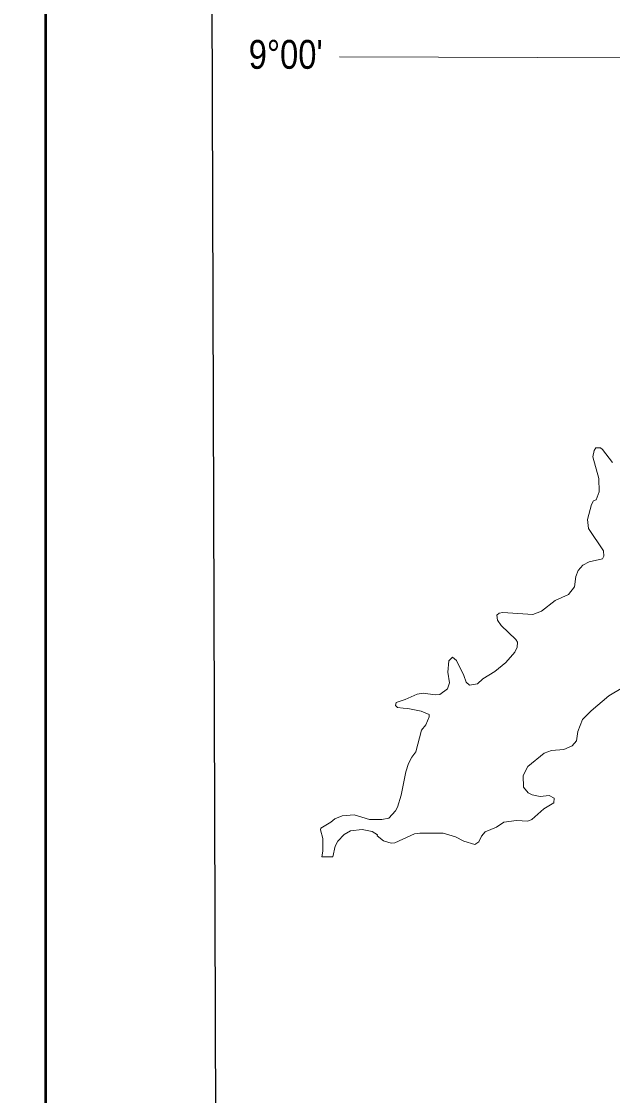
# Model space of a CAD drawing. Extents: x -1643653 to 4543381, y 1624270 to 13878484.
# Drawn here: x 559789 to 570038, y 8987135 to 9005760 of the extents above; entities that cross this region are included whole.
import ezdxf
from ezdxf.enums import TextEntityAlignment as Align

# ---------------------------------------------------------------- set-up
doc = ezdxf.new("R2010")
doc.units = 0
doc.header["$LTSCALE"] = 200
for name, color, linetype, lineweight in [('1', 7, 'Continuous', 13), ('25', 7, 'Continuous', 13), ('3', 7, 'Continuous', 13), ('60', 7, 'Continuous', 13)]:
    doc.layers.add(name, color=color, linetype=linetype, lineweight=lineweight)
doc.layers.add('46', color=7, linetype='Continuous')

msp = doc.modelspace()

# ---------------------------------------------------------------- linework, layer by layer
at = {"layer": '1'}
msp.add_lwpolyline([(565303.2, 9005146.6), (664889.8, 9004806.7), (719872.1, 9004543.9), (790635.8, 9004109)], dxfattribs=at)
at = {"layer": '25'}
for points in [[(570039.3, 8998110.8), (569862.2, 8998339.7), (569828.8, 8998363.9), (569747.5, 8998367.9), (569719.3, 8998318.1), (569695.6, 8998210), (569803.5, 8997832.4), (569805.7, 8997600.4), (569753.7, 8997466.5), (569708.6, 8997447), (569671.8, 8997384.4), (569607, 8997125.3), (569624.2, 8996969.4), (569883.5, 8996580.5), (569890, 8996489.7), (569862.1, 8996442.2), (569634.2, 8996387.6), (569524.8, 8996331.6), (569444.9, 8996241), (569401.6, 8996135.2), (569377.7, 8995955.6), (569276.2, 8995821.7), (569042.7, 8995719.9), (568806.8, 8995531.7), (568653.5, 8995475.6), (568134.7, 8995512.3), (568072.2, 8995501.6), (568030.8, 8995462.5), (568041.7, 8995378.5), (568108.6, 8995287.8), (568364, 8995043), (568387.6, 8994997.6), (568385.5, 8994911.7), (568342.3, 8994825.1), (568190.7, 8994643.1), (567996.1, 8994487.5), (567788.8, 8994357.9), (567698, 8994275.9), (567560, 8994252.1), (567499.2, 8994304.1), (567462.2, 8994418.7), (567330.6, 8994677.7), (567263.6, 8994734), (567200.7, 8994675.1), (567183.6, 8994478), (567209.4, 8994288.5), (567174.9, 8994185.2), (567041.5, 8994087.6), (566962.8, 8994081.3), (566755.8, 8994109.3), (566652.7, 8994094.4), (566443.9, 8994001.2), (566287.2, 8993950.5), (566277.5, 8993895.3), (566309.1, 8993863.6), (566406.3, 8993853.8)], [(570039.3, 8998110.8), (569862.2, 8998339.7), (569828.8, 8998363.9), (569747.5, 8998367.9), (569719.3, 8998318.1), (569695.6, 8998210), (569803.5, 8997832.4), (569805.7, 8997600.4), (569753.7, 8997466.5), (569708.6, 8997447), (569671.8, 8997384.4), (569607, 8997125.3), (569624.2, 8996969.4), (569883.5, 8996580.5), (569890, 8996489.7), (569862.1, 8996442.2), (569634.2, 8996387.6), (569524.8, 8996331.6), (569444.9, 8996241), (569401.6, 8996135.2), (569377.7, 8995955.6), (569276.2, 8995821.7), (569042.7, 8995719.9), (568806.8, 8995531.7), (568653.5, 8995475.6), (568134.7, 8995512.3), (568072.2, 8995501.6), (568030.8, 8995462.5), (568041.7, 8995378.5), (568108.6, 8995287.8), (568364, 8995043), (568387.6, 8994997.6), (568385.5, 8994911.7), (568342.3, 8994825.1), (568190.7, 8994643.1), (567996.1, 8994487.5), (567788.8, 8994357.9), (567698, 8994275.9), (567560, 8994252.1), (567499.2, 8994304.1), (567462.2, 8994418.7), (567330.6, 8994677.7), (567263.6, 8994734), (567200.7, 8994675.1), (567183.6, 8994478), (567209.4, 8994288.5), (567174.9, 8994185.2), (567041.5, 8994087.6), (566962.8, 8994081.3), (566755.8, 8994109.3), (566652.7, 8994094.4), (566443.9, 8994001.2), (566287.2, 8993950.5), (566277.5, 8993895.3), (566309.1, 8993863.6), (566406.3, 8993853.8)], [(568487.1, 8992684.5), (568569.1, 8992838), (568854.8, 8993074), (568977.6, 8993117), (569194, 8993136.6), (569341.2, 8993199.5), (569413.7, 8993286.4), (569438.4, 8993446), (569516.9, 8993653.7), (569666.9, 8993803.6), (569976.6, 8994064), (570432.9, 8994338.6)], [(568487.1, 8992684.5), (568569.1, 8992838), (568854.8, 8993074), (568977.6, 8993117), (569194, 8993136.6), (569341.2, 8993199.5), (569413.7, 8993286.4), (569438.4, 8993446), (569516.9, 8993653.7), (569666.9, 8993803.6), (569976.6, 8994064), (570432.9, 8994338.6)], [(566406.3, 8993853.8), (566487.5, 8993845.6), (566720.4, 8993798.2), (566856.8, 8993741.9), (566861.3, 8993701.1), (566803.3, 8993560.8), (566725.3, 8993467.3), (566628, 8993095.8), (566556.6, 8993002.5), (566500.5, 8992892.5), (566452.8, 8992749.4), (566371.7, 8992344.8), (566307.9, 8992133.6), (566273.3, 8992070.6), (566159, 8991941.3), (566037.8, 8991923.8), (565822.3, 8991921.6), (565557.9, 8992003.8), (565347.2, 8991985.1), (565224.8, 8991932.3), (565151.5, 8991872), (564980.8, 8991770.3), (564976.4, 8991740.3), (564976.4, 8991740.3), (565017.4, 8991591.1), (565017.4, 8991374.7), (564994.9, 8991274.5), (565186.5, 8991274.5)], [(566406.3, 8993853.8), (566487.5, 8993845.6), (566720.4, 8993798.2), (566856.8, 8993741.9), (566861.3, 8993701.1), (566803.3, 8993560.8), (566725.3, 8993467.3), (566628, 8993095.8), (566556.6, 8993002.5), (566500.5, 8992892.5), (566452.8, 8992749.4), (566371.7, 8992344.8), (566307.9, 8992133.6), (566273.3, 8992070.6), (566159, 8991941.3), (566037.8, 8991923.8), (565822.3, 8991921.6), (565557.9, 8992003.8), (565347.2, 8991985.1), (565224.8, 8991932.3), (565151.5, 8991872), (564980.8, 8991770.3), (564976.4, 8991740.3), (564976.4, 8991740.3), (565017.4, 8991591.1), (565017.4, 8991374.7), (564994.9, 8991274.5), (565186.5, 8991274.5)], [(565186.5, 8991274.5), (565229.4, 8991456.8), (565277, 8991543.6), (565385, 8991662.2), (565495.2, 8991724.9), (565699.6, 8991750.3), (565868.8, 8991714.1), (565962.8, 8991656.3), (565956, 8991638.4), (566069.6, 8991550.2), (566202.1, 8991510.9), (566262.2, 8991518.1), (566602.6, 8991670.9), (566699.3, 8991686), (567101.1, 8991683.8), (567313.2, 8991623.3), (567457.9, 8991543.5), (567647.8, 8991487.2), (567719.8, 8991534.9), (567767.4, 8991634.3), (567827.8, 8991705.4), (568027.3, 8991790.1), (568156.3, 8991874), (568371.7, 8991906.5), (568571.6, 8991889.4), (568638.4, 8991921.7), (568847.5, 8992104.9), (569018.9, 8992209.7), (569025.4, 8992289.9), (568938.9, 8992336.7), (568783.5, 8992319.5), (568643, 8992349.7), (568576.9, 8992385), (568495.8, 8992479.4), (568487.1, 8992684.5)], [(565186.5, 8991274.5), (565229.4, 8991456.8), (565277, 8991543.6), (565385, 8991662.2), (565495.2, 8991724.9), (565699.6, 8991750.3), (565868.8, 8991714.1), (565962.8, 8991656.3), (565956, 8991638.4), (566069.6, 8991550.2), (566202.1, 8991510.9), (566262.2, 8991518.1), (566602.6, 8991670.9), (566699.3, 8991686), (567101.1, 8991683.8), (567313.2, 8991623.3), (567457.9, 8991543.5), (567647.8, 8991487.2), (567719.8, 8991534.9), (567767.4, 8991634.3), (567827.8, 8991705.4), (568027.3, 8991790.1), (568156.3, 8991874), (568371.7, 8991906.5), (568571.6, 8991889.4), (568638.4, 8991921.7), (568847.5, 8992104.9), (569018.9, 8992209.7), (569025.4, 8992289.9), (568938.9, 8992336.7), (568783.5, 8992319.5), (568643, 8992349.7), (568576.9, 8992385), (568495.8, 8992479.4), (568487.1, 8992684.5)]]:
    msp.add_lwpolyline(points, dxfattribs=at)
at = {"layer": '3', "lineweight": 53}
msp.add_lwpolyline([(840307.3, 9029887.8), (840307.3, 8886387.8), (560211.7, 8886387.8), (560211.7, 9029887.8)], close=True, dxfattribs=at)
at = {"layer": '3', "lineweight": 25}
msp.add_lwpolyline([(563033.9, 9026438.8), (793061.1, 9026438.8), (793495.6, 8889836.8), (563468.3, 8889836.8)], close=True, dxfattribs=at)
at = {"layer": '60', "lineweight": 25}
msp.add_spline([(814781, 9009175.5), (814787.2, 9009173.4), (814796.9, 9009173.4), (814799.4, 9009172.4), (814805.1, 9009174.5), (814805.6, 9009176.5), (814811.7, 9009179.5), (814811.7, 9009179.5), (814801.5, 9009181), (814790.7, 9009181.5), (814784.1, 9009183.1), (814777.4, 9009185.1), (814778.4, 9009175.5)], degree=3, dxfattribs=at)

# ---------------------------------------------------------------- texts
at = {"layer": '46', "width": 0.85}
msp.add_text("9°00'", height=500, dxfattribs=at).set_placement((564370.9, 9004939.3), align=Align.CENTER)

doc.saveas('drawing.dxf')
